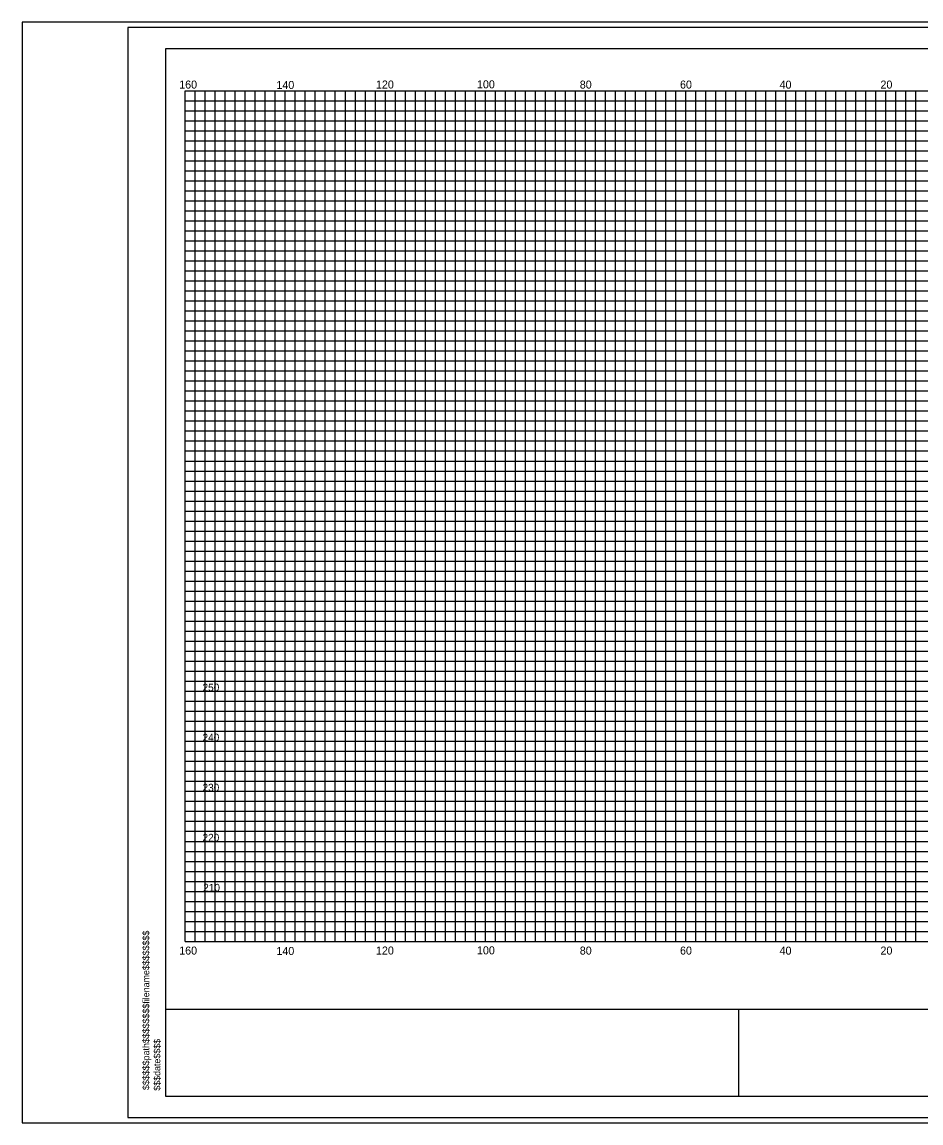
# Model space of a CAD drawing. Extents: x 967 to 1326, y 964 to 1744.
# Drawn here: x 967.4 to 1147, y 1523.7 to 1743.7 of the extents above; entities that cross this region are included whole.
import ezdxf

# ---------------------------------------------------------------- set-up
doc = ezdxf.new("R2010")
doc.units = 0
for name, color, linetype in [('Default', 7, 'Continuous'), ('RD_PD_PaveShd', 7, 'Continuous'), ('RD_XS_CurbBase', 7, 'Continuous'), ('RD_XS_TX_Elev_PR', 7, 'Continuous'), ('RD_XS_TX_MkPT', 7, 'Continuous'), ('RD_XS_TX_Slope', 7, 'Continuous'), ('RD_XS_TX_TOC', 7, 'Continuous')]:
    doc.layers.add(name, color=color, linetype=linetype)

msp = doc.modelspace()

# ---------------------------------------------------------------- linework, layer by layer
at = {"layer": 'RD_PD_PaveShd'}
for p, q in [((996.11, 1528.98), (996.11, 1738.46)), ((996.11, 1738.46), (1323.89, 1738.46)), ((996.11, 1546.49), (1323.89, 1546.49)), ((1110.59, 1528.98), (1110.59, 1546.56)), ((1323.89, 1528.98), (996.11, 1528.98))]:
    msp.add_line(p, q, dxfattribs=at)
at = {"layer": 'RD_XS_CurbBase'}
msp.add_lwpolyline([(967.41, 1523.72), (1326.28, 1523.72), (1326.28, 1743.72), (967.41, 1743.72)], close=True, dxfattribs=at)
at = {"layer": 'RD_XS_TX_Elev_PR'}
for p, q in [((1000, 1730), (1320, 1730)), ((1000, 1560), (1000, 1730)), ((1010, 1560), (1010, 1730)), ((1020, 1560), (1020, 1730)), ((1030, 1560), (1030, 1730)), ((1040, 1560), (1040, 1730)), ((1050, 1560), (1050, 1730)), ((1060, 1560), (1060, 1730)), ((1070, 1560), (1070, 1730)), ((1080, 1560), (1080, 1730)), ((1090, 1560), (1090, 1730)), ((1100, 1560), (1100, 1730)), ((1110, 1560), (1110, 1730)), ((1120, 1560), (1120, 1730)), ((1130, 1560), (1130, 1730)), ((1140, 1560), (1140, 1730)), ((1000, 1720), (1320, 1720)), ((1000, 1710), (1320, 1710)), ((1000, 1700), (1320, 1700)), ((1000, 1690), (1320, 1690)), ((1000, 1680), (1320, 1680)), ((1000, 1670), (1320, 1670)), ((1000, 1660), (1320, 1660)), ((1000, 1650), (1320, 1650)), ((1000, 1640), (1320, 1640)), ((1000, 1630), (1320, 1630)), ((1000, 1620), (1320, 1620)), ((1000, 1610), (1320, 1610)), ((1000, 1600), (1320, 1600)), ((1000, 1590), (1320, 1590)), ((1000, 1580), (1320, 1580)), ((1000, 1570), (1320, 1570)), ((1000, 1560), (1320, 1560))]:
    msp.add_line(p, q, dxfattribs=at)
at = {"layer": 'RD_XS_TX_Slope'}
for p, q in [((1002, 1560), (1002, 1730)), ((1004, 1560), (1004, 1730)), ((1006, 1560), (1006, 1730)), ((1008, 1560), (1008, 1730)), ((1012, 1560), (1012, 1730)), ((1014, 1560), (1014, 1730)), ((1016, 1560), (1016, 1730)), ((1018, 1560), (1018, 1730)), ((1022, 1560), (1022, 1730)), ((1024, 1560), (1024, 1730)), ((1026, 1560), (1026, 1730)), ((1028, 1560), (1028, 1730)), ((1032, 1560), (1032, 1730)), ((1034, 1560), (1034, 1730)), ((1036, 1560), (1036, 1730)), ((1038, 1560), (1038, 1730)), ((1042, 1560), (1042, 1730)), ((1044, 1560), (1044, 1730)), ((1046, 1560), (1046, 1730)), ((1048, 1560), (1048, 1730)), ((1052, 1560), (1052, 1730)), ((1054, 1560), (1054, 1730)), ((1056, 1560), (1056, 1730)), ((1058, 1560), (1058, 1730)), ((1062, 1560), (1062, 1730)), ((1064, 1560), (1064, 1730)), ((1066, 1560), (1066, 1730)), ((1068, 1560), (1068, 1730)), ((1072, 1560), (1072, 1730)), ((1074, 1560), (1074, 1730)), ((1076, 1560), (1076, 1730)), ((1078, 1560), (1078, 1730)), ((1082, 1560), (1082, 1730)), ((1084, 1560), (1084, 1730)), ((1086, 1560), (1086, 1730)), ((1088, 1560), (1088, 1730)), ((1092, 1560), (1092, 1730)), ((1094, 1560), (1094, 1730)), ((1096, 1560), (1096, 1730)), ((1098, 1560), (1098, 1730)), ((1102, 1560), (1102, 1730)), ((1104, 1560), (1104, 1730)), ((1106, 1560), (1106, 1730)), ((1108, 1560), (1108, 1730)), ((1112, 1560), (1112, 1730)), ((1114, 1560), (1114, 1730)), ((1116, 1560), (1116, 1730)), ((1118, 1560), (1118, 1730)), ((1122, 1560), (1122, 1730)), ((1124, 1560), (1124, 1730)), ((1126, 1560), (1126, 1730)), ((1128, 1560), (1128, 1730)), ((1132, 1560), (1132, 1730)), ((1134, 1560), (1134, 1730)), ((1136, 1560), (1136, 1730)), ((1138, 1560), (1138, 1730)), ((1142, 1560), (1142, 1730)), ((1144, 1560), (1144, 1730)), ((1146, 1560), (1146, 1730)), ((1000, 1728), (1320, 1728)), ((1000, 1726), (1320, 1726)), ((1000, 1724), (1320, 1724)), ((1000, 1722), (1320, 1722)), ((1000, 1718), (1320, 1718)), ((1000, 1716), (1320, 1716)), ((1000, 1714), (1320, 1714)), ((1000, 1712), (1320, 1712)), ((1000, 1708), (1320, 1708)), ((1000, 1706), (1320, 1706)), ((1000, 1704), (1320, 1704)), ((1000, 1702), (1320, 1702)), ((1000, 1698), (1320, 1698)), ((1000, 1696), (1320, 1696)), ((1000, 1694), (1320, 1694)), ((1000, 1692), (1320, 1692)), ((1000, 1688), (1320, 1688)), ((1000, 1686), (1320, 1686)), ((1000, 1684), (1320, 1684)), ((1000, 1682), (1320, 1682)), ((1000, 1678), (1320, 1678)), ((1000, 1676), (1320, 1676)), ((1000, 1674), (1320, 1674)), ((1000, 1672), (1320, 1672)), ((1000, 1668), (1320, 1668)), ((1000, 1666), (1320, 1666)), ((1000, 1664), (1320, 1664)), ((1000, 1662), (1320, 1662)), ((1000, 1658), (1320, 1658)), ((1000, 1656), (1320, 1656)), ((1000, 1654), (1320, 1654)), ((1000, 1652), (1320, 1652)), ((1000, 1648), (1320, 1648)), ((1000, 1646), (1320, 1646)), ((1000, 1644), (1320, 1644)), ((1000, 1642), (1320, 1642)), ((1000, 1638), (1320, 1638)), ((1000, 1636), (1320, 1636)), ((1000, 1634), (1320, 1634)), ((1000, 1632), (1320, 1632)), ((1000, 1628), (1320, 1628)), ((1000, 1626), (1320, 1626)), ((1000, 1624), (1320, 1624)), ((1000, 1622), (1320, 1622)), ((1000, 1618), (1320, 1618)), ((1000, 1616), (1320, 1616)), ((1000, 1614), (1320, 1614)), ((1000, 1612), (1320, 1612)), ((1000, 1608), (1320, 1608)), ((1000, 1606), (1320, 1606)), ((1000, 1604), (1320, 1604)), ((1000, 1602), (1320, 1602)), ((1000, 1598), (1320, 1598)), ((1000, 1596), (1320, 1596)), ((1000, 1594), (1320, 1594)), ((1000, 1592), (1320, 1592)), ((1000, 1588), (1320, 1588)), ((1000, 1586), (1320, 1586)), ((1000, 1584), (1320, 1584)), ((1000, 1582), (1320, 1582)), ((1000, 1578), (1320, 1578)), ((1000, 1576), (1320, 1576)), ((1000, 1574), (1320, 1574)), ((1000, 1572), (1320, 1572)), ((1000, 1568), (1320, 1568)), ((1000, 1566), (1320, 1566)), ((1000, 1564), (1320, 1564)), ((1000, 1562), (1320, 1562))]:
    msp.add_line(p, q, dxfattribs=at)
at = {"layer": 'RD_XS_TX_TOC'}
for points in [[(967.41, 1523.72), (1326.28, 1523.72), (1326.28, 1743.72), (967.41, 1743.72)], [(988.52, 1524.84), (1326.28, 1524.84), (1326.28, 1742.6), (988.52, 1742.6)]]:
    msp.add_lwpolyline(points, close=True, dxfattribs=at)

# ---------------------------------------------------------------- texts
at = {"layer": 'Default'}
for s, p in [('250', (1003.47, 1610)), ('240', (1003.47, 1600)), ('230', (1003.47, 1590)), ('220', (1003.47, 1580)), ('210', (1003.61, 1570))]:
    msp.add_text(s, height=1.5, dxfattribs=at).set_placement(p)
for s, p in [('$$$$$$path$$$$$$$$filename$$$$$$$$', (992.83, 1530.31)), ('$$$date$$$$', (995.04, 1530.17))]:
    msp.add_text(s, height=1.3258, rotation=90, dxfattribs=at).set_placement(p)
at = {"layer": 'RD_XS_TX_MkPT'}
for s, p in [('160', (998.81, 1730.42)), ('140', (1018.23, 1730.34)), ('120', (1038.12, 1730.43)), ('100', (1058.3, 1730.47)), ('80', (1078.84, 1730.42)), ('60', (1098.86, 1730.42)), ('40', (1118.75, 1730.41)), ('20', (1138.91, 1730.42)), ('160', (998.81, 1557.37)), ('140', (1018.23, 1557.29)), ('120', (1038.12, 1557.38)), ('100', (1058.3, 1557.42)), ('80', (1078.84, 1557.37)), ('60', (1098.86, 1557.37)), ('40', (1118.75, 1557.36)), ('20', (1138.91, 1557.37))]:
    msp.add_text(s, height=1.6, dxfattribs=at).set_placement(p)

doc.saveas('drawing.dxf')
